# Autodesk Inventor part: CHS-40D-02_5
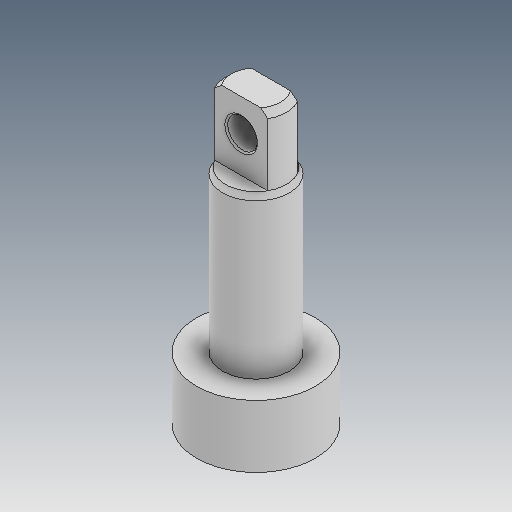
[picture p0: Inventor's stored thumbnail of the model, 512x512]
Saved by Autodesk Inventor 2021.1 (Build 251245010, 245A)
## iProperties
Created: 2019-04
Part Number: CHS-40D-02_5
Material: Ogólny
Document SubType Name: Modeling
Designer: user
Density: 1 g/cm^3
Appearance: Domyślna
Author: user
Revision Number: ÈÎºÎ
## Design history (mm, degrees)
feature "ÊäÈë1"
feature "ÊäÈë2"
node "Bryła1"
node "Bryła2"
